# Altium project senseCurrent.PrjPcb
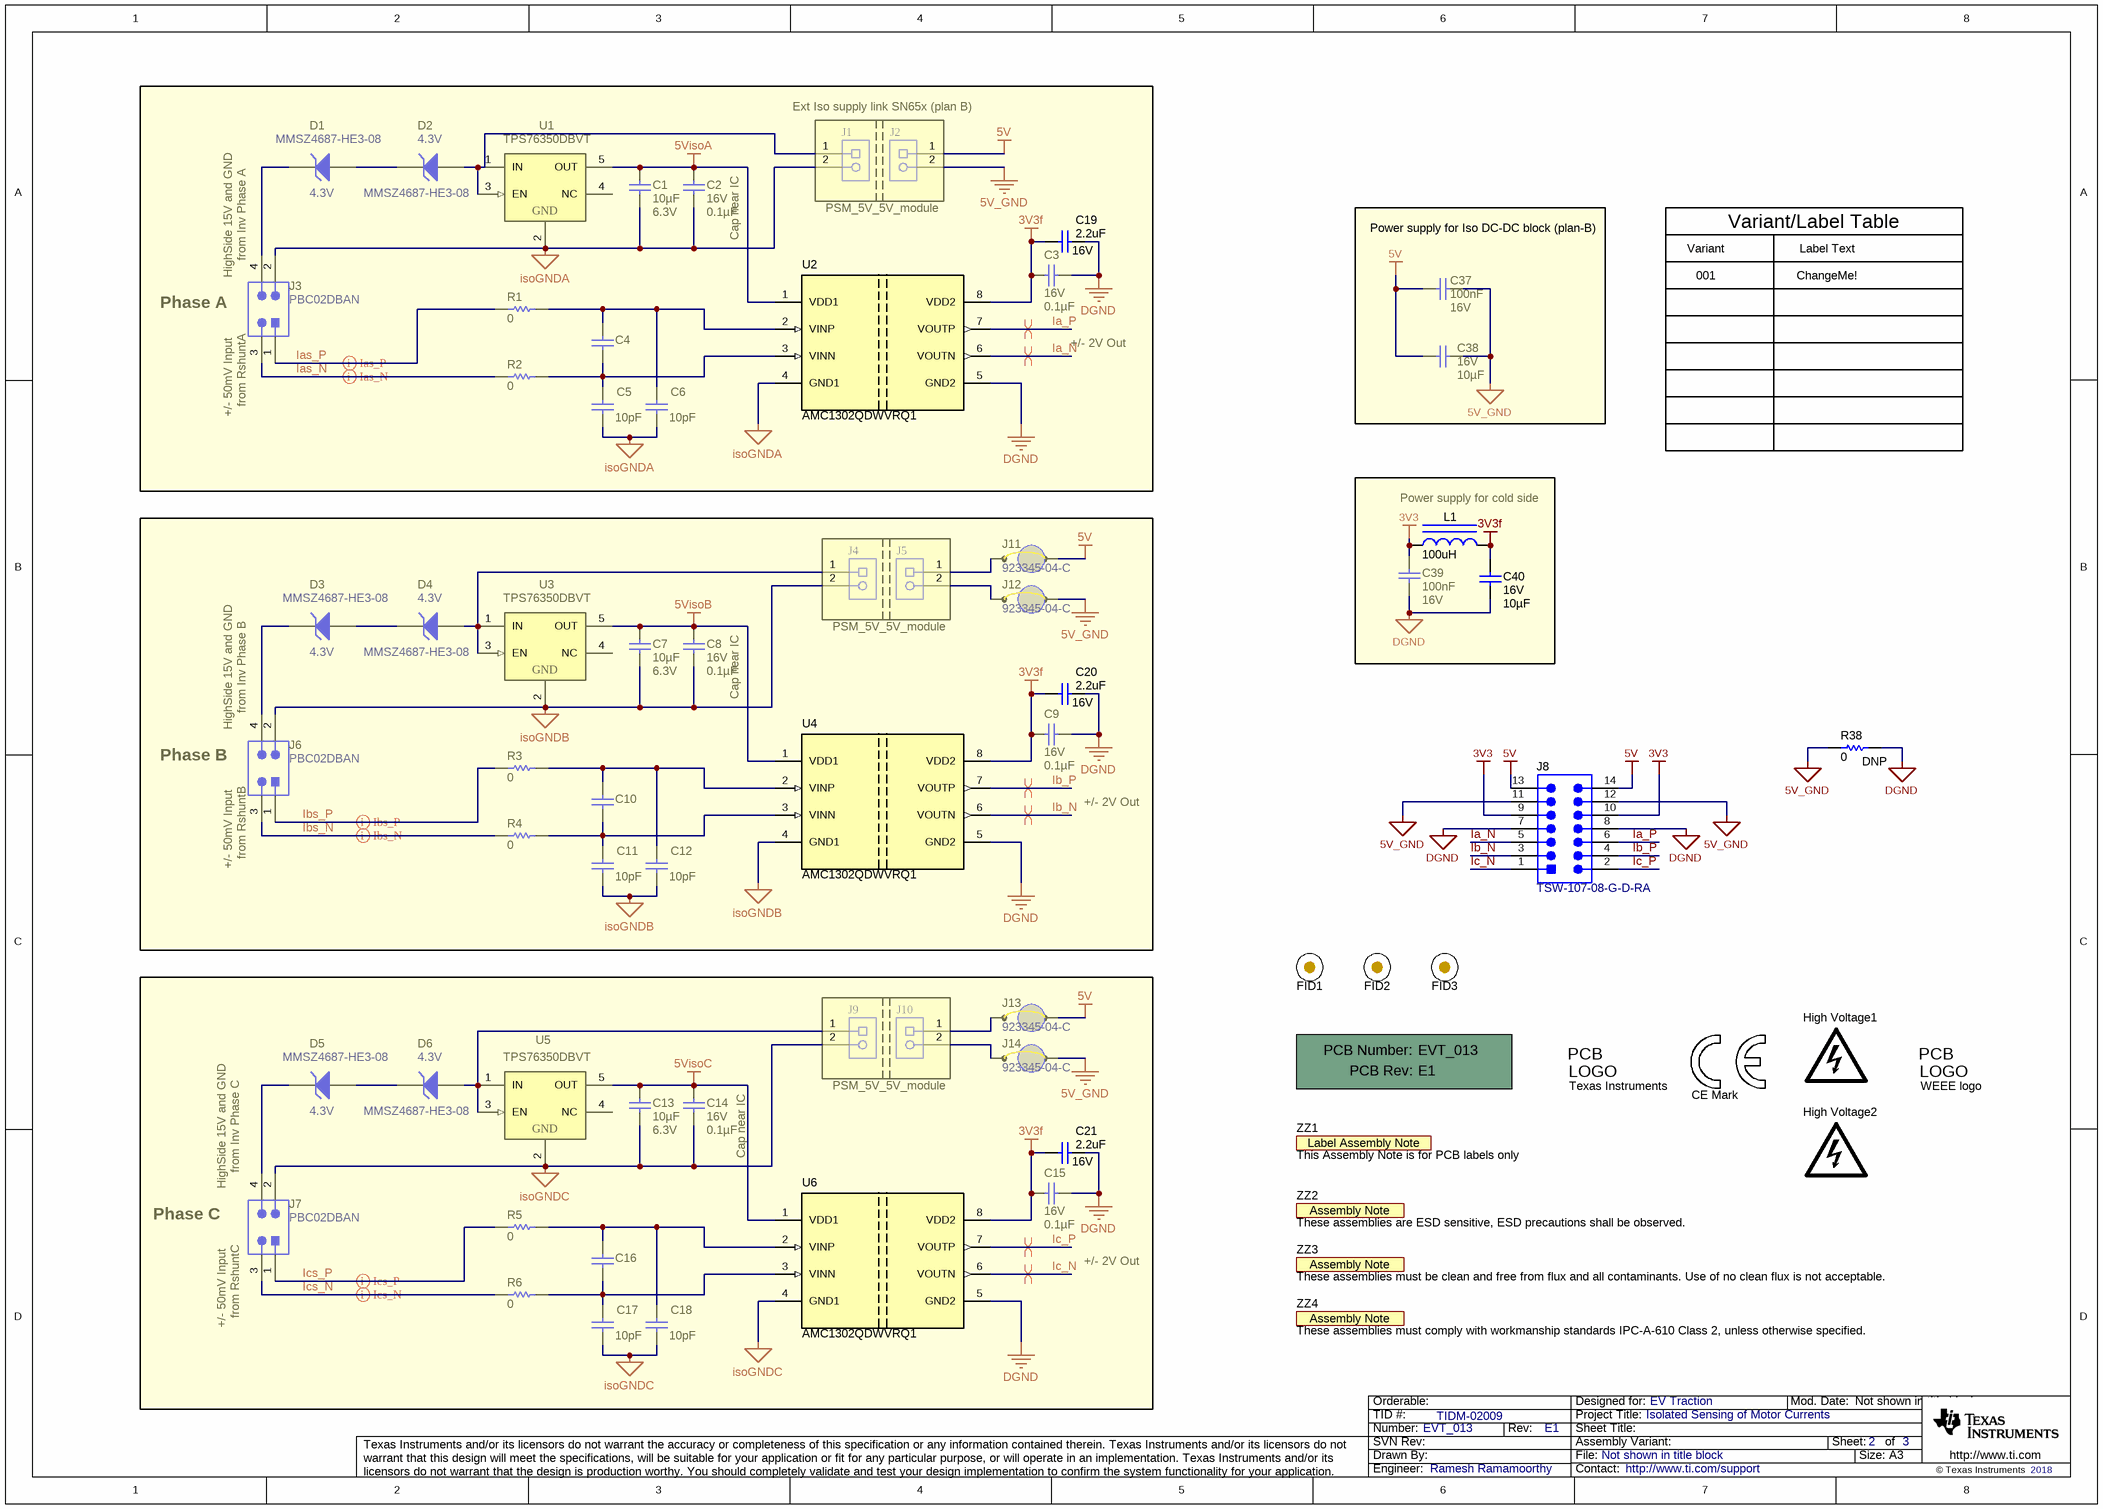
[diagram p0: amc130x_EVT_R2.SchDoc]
CopyrightYear: 2018; PCB_Layout: Ramesh Ramamoorthy; PCB_Rev: E1; PRJ_Customer: EV Traction; PRJ_Engineer: Ramesh Ramamoorthy; PRJ_Number: EVT_013; PRJ_Title: Isolated Sensing of Motor Currents; SCH_Rev: E1; TechSupport: http://www.ti.com/support; TID: TIDM-02009
1 sheet, 72 parts. Net scope: global (net labels, ports and power ports of the same name join across sheets).
Board file: amc130x_EVT_r4.PcbDoc

## Sheet amc130x_EVT_R2.SchDoc
size A3; Date: Not shown in title block; ApprovedBy: Not shown in title block; CheckedBy: Not shown in title block; Author: Not shown in title block; CompanyName: Not shown in title block; Engineer: Not shown in title block; Organization: Not shown in title block; Address1: Not shown in title block; Address2: Not shown in title block; Address3: Not shown in title block; Address4: Not shown in title block; DocumentNumber: 2; Revision: Use project parameter SCH_Rev; SheetNumber: 2; SheetTotal: 3; PageSetup: Record=PageOptions¦CenterHorizontal=True¦CenterVertical=True¦PrintScale=1.00¦XCorrection=1.00¦YCorrection=1.00¦PrintKind=0¦BorderSize=5000000¦LeftOffset=0¦BottomOffset=0¦Orientation=2¦PaperLength=1000¦PaperWidth=1000¦Scale=100¦PaperSource=15¦PrintQuality=600¦MediaType=1¦DitherType=10¦PaperKind=Letter¦PrintScaleMode=1

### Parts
!PCB  Printed Circuit Board  (value not drawn)  (mechanical)
C1  Cap_F: 10µF  VDC_V: 6.3V  [0805_HV]  (hidden comment: GRM21BR70J106KE76L)
C2  VDC_V: 16V  ValueDisplayed: 0.1µF  [1206]  (hidden comment: 1206YC104KAT2A)
C3  VDC_V: 16V  ValueDisplayed: 0.1µF  [1206]  (hidden comment: 1206YC104KAT2A)
C4  06035A331JAT2A  [0603]  (value not drawn)
C5  ValueDisplayed: 10pF  [0603]  (hidden comment: 06035A100JAT2A)
C6  ValueDisplayed: 10pF  [0603]  (hidden comment: 06035A100JAT2A)
C7  Cap_F: 10µF  VDC_V: 6.3V  [0805_HV]  (hidden comment: GRM21BR70J106KE76L)
C8  VDC_V: 16V  ValueDisplayed: 0.1µF  [1206]  (hidden comment: 1206YC104KAT2A)
C9  VDC_V: 16V  ValueDisplayed: 0.1µF  [1206]  (hidden comment: 1206YC104KAT2A)
C10  06035A331JAT2A  [0603]  (value not drawn)
C11  ValueDisplayed: 10pF  [0603]  (hidden comment: 06035A100JAT2A)
C12  ValueDisplayed: 10pF  [0603]  (hidden comment: 06035A100JAT2A)
C13  Cap_F: 10µF  VDC_V: 6.3V  [0805_HV]  (hidden comment: GRM21BR70J106KE76L)
C14  VDC_V: 16V  ValueDisplayed: 0.1µF  [1206]  (hidden comment: 1206YC104KAT2A)
C15  VDC_V: 16V  ValueDisplayed: 0.1µF  [1206]  (hidden comment: 1206YC104KAT2A)
C16  06035A331JAT2A  [0603]  (value not drawn)
C17  ValueDisplayed: 10pF  [0603]  (hidden comment: 06035A100JAT2A)
C18  ValueDisplayed: 10pF  [0603]  (hidden comment: 06035A100JAT2A)
C19  VDC_V: 16V  ValueDisplayed: 2.2uF  [1206]  (hidden comment: GRM31MR71C225KA35L)
C20  VDC_V: 16V  ValueDisplayed: 2.2uF  [1206]  (hidden comment: GRM31MR71C225KA35L)
C21  VDC_V: 16V  ValueDisplayed: 2.2uF  [1206]  (hidden comment: GRM31MR71C225KA35L)
C37  Cap_F: 100nF  VDC_V: 16V  [0603]  (hidden comment: CGJ3E2X7R1C104K080AA)
C38  VDC_V: 16V  ValueDisplayed: 10µF  [0603]  (hidden comment: GRM188R61C106KAALD)
C39  Cap_F: 100nF  VDC_V: 16V  [0603]  (hidden comment: CGJ3E2X7R1C104K080AA)
C40  VDC_V: 16V  ValueDisplayed: 10µF  [0603]  (hidden comment: GRM188R61C106KAALD)
D1  MMSZ4687-HE3-08  value 4.3V  [SOD-123]
D2  MMSZ4687-HE3-08  value 4.3V  [SOD-123]
D3  MMSZ4687-HE3-08  value 4.3V  [SOD-123]
D4  MMSZ4687-HE3-08  value 4.3V  [SOD-123]
D5  MMSZ4687-HE3-08  value 4.3V  [SOD-123]
D6  MMSZ4687-HE3-08  value 4.3V  [SOD-123]
FID1  Fiducial  [Fiducial10-20]  (value not drawn)
FID2  Fiducial  [Fiducial10-20]  (value not drawn)
FID3  Fiducial  [Fiducial10-20]  (value not drawn)
High_Voltage1  DANGER HIGH VOLTAGE  [IEC_HighVoltage_Small]  (value not drawn)  (no BOM)
High_Voltage2  DANGER HIGH VOLTAGE  [IEC_HighVoltage_Small]  (value not drawn)  (no BOM)
J1  5-534206-1  [CONN_534206-1]  (value not drawn)
J2  5-534206-1  [CONN_534206-1]  (value not drawn)
J3  PBC02DBAN  [Sullins_PxC02DBAN]
J4  5-534206-1  [CONN_534206-1]  (value not drawn)
J5  5-534206-1  [CONN_534206-1]  (value not drawn)
J6  PBC02DBAN  [Sullins_PxC02DBAN]
J7  PBC02DBAN  [Sullins_PxC02DBAN]
J8  TSW-107-08-G-D-RA  [TSW-107-08-G-D-RA]
J9  5-534206-1  [CONN_534206-1]  (value not drawn)
J10  5-534206-1  [CONN_534206-1]  (value not drawn)
J11  923345-04-C  [3M_923345-04-C]
J12  923345-04-C  [3M_923345-04-C]
J13  923345-04-C  [3M_923345-04-C]
J14  923345-04-C  [3M_923345-04-C]
L1  ValueDisplayed: 100uH  [MSS6122]  (hidden comment: MSS6122-104MLB)
Logo1  Texas Instruments  [TI_Stacked_Overlay_Small]  (no BOM)
Logo2  CE Mark  [CE_Mark_5mm]  (no BOM)
Logo3  WEEE logo  [WEEE_Minimum]  (no BOM)
R1  ValueDisplayed: 0  [0603]  (hidden comment: MCR03EZPJ000)
R2  ValueDisplayed: 0  [0603]  (hidden comment: MCR03EZPJ000)
R3  ValueDisplayed: 0  [0603]  (hidden comment: MCR03EZPJ000)
R4  ValueDisplayed: 0  [0603]  (hidden comment: MCR03EZPJ000)
R5  ValueDisplayed: 0  [0603]  (hidden comment: MCR03EZPJ000)
R6  ValueDisplayed: 0  [0603]  (hidden comment: MCR03EZPJ000)
R38  ValueDisplayed: 0  [0603]  (hidden comment: ERJ-3GEY0R00V)
U1  TPS76350DBVT  [DBV0005A_N]
U2  AMC1302QDWVRQ1  [DWV0008A]
U3  TPS76350DBVT  [DBV0005A_N]
U4  AMC1302QDWVRQ1  [DWV0008A]
U5  TPS76350DBVT  [DBV0005A_N]
U6  AMC1302QDWVRQ1  [DWV0008A]
ZZ1  This Assembly Note is for PCB labels only  [AssemblyNoteLabel]  (no BOM)
ZZ2  These assemblies are ESD sensitive, ESD precautions shall be observed.  [AssemblyNote]  (no BOM)
ZZ3  These assemblies must be clean and free from flux and all contaminants. Use of no clean flux is not acceptable.  [AssemblyNote]  (no BOM)
ZZ4  These assemblies must comply with workmanship standards IPC-A-610 Class 2, unless otherwise specified.  [AssemblyNote]  (no BOM)

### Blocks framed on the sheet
Phase A: C1-C6 C19 D1 D2 J3 R1 R2 U1 U2
Ext Iso supply link SN65x (plan B): J1 J2
Power supply for Iso DC-DC block (plan-B): C37 C38
Power supply for cold side: C39 C40 L1
Phase B: C7-C12 C20 D3 D4 J4-J6 J11 J12 R3 R4 U3 U4
Phase C: C13-C18 C21 D5 D6 J7 J9 J10 J13 J14 R5 R6 U5 U6

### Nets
3V3: C39.2 J8.9 J8.10 L1.1
3V3f: C3.2 C9.2 C15.2 C19.2 C20.2 C21.2 C40.2 L1.2 U2.8(VDD2) U4.8(VDD2) U6.8(VDD2)
5V: C37.2 C38.2 J2.1 J8.13 J8.14 J11.2 J13.2
5V_GND: C37.1 C38.1 J2.2 J8.11 J8.12 J12.2 J14.2 R38.1
5VisoA: C1.2 C2.1 U1.5(OUT) U2.1(VDD1)
5VisoB: C7.2 C8.1 U3.5(OUT) U4.1(VDD1)
5VisoC: C13.2 C14.1 U5.5(OUT) U6.1(VDD1)
DGND: C3.1 C9.1 C15.1 C19.1 C20.1 C21.1 C39.1 C40.1 J8.7 J8.8 R38.2 U2.5(GND2) U4.5(GND2) U6.5(GND2)
isoGNDA: C1.1 C2.2 C5.2 C6.2 J1.2 J3.2 U1.2(GND) U2.4(GND1)
isoGNDB: C7.1 C8.2 C11.2 C12.2 J4.2 J6.2 U3.2(GND) U4.4(GND1)
isoGNDC: C13.1 C14.2 C17.2 C18.2 J7.2 J9.2 U5.2(GND) U6.4(GND1)
Ia_N: J8.5 U2.6(VOUTN)
Ia_P: J8.6 U2.7(VOUTP)
Ias_N: J3.3 R2.1
Ias_P: J3.1 R1.1
Ib_N: J8.3 U4.6(VOUTN)
Ib_P: J8.4 U4.7(VOUTP)
Ibs_N: J6.3 R4.1
Ibs_P: J6.1 R3.1
Ic_N: J8.1 U6.6(VOUTN)
Ic_P: J8.2 U6.7(VOUTP)
Ics_N: J7.3 R6.1
Ics_P: J7.1 R5.1
NetC4_1: C4.1 C6.1 R1.2 U2.2(VINP)
NetC4_2: C4.2 C5.1 R2.2 U2.3(VINN)
NetC10_1: C10.1 C12.1 R3.2 U4.2(VINP)
NetC10_2: C10.2 C11.1 R4.2 U4.3(VINN)
NetC16_1: C16.1 C18.1 R5.2 U6.2(VINP)
NetC16_2: C16.2 C17.1 R6.2 U6.3(VINN)
NetD1_1: D1.1(K) J3.4
NetD1_2: D1.2(A) D2.1(K)
NetD2_2: D2.2(A) J1.1 U1.1(IN) U1.3(EN)
NetD3_1: D3.1(K) J6.4
NetD3_2: D3.2(A) D4.1(K)
NetD4_2: D4.2(A) J4.1 U3.1(IN) U3.3(EN)
NetD5_1: D5.1(K) J7.4
NetD5_2: D5.2(A) D6.1(K)
NetD6_2: D6.2(A) J9.1 U5.1(IN) U5.3(EN)
NetJ5_1: J5.1 J11.1
NetJ5_2: J5.2 J12.1
NetJ10_1: J10.1 J13.1
NetJ10_2: J10.2 J14.1

Not connected (* = marked no-connect by the designer): U1 4(NC); U3 4(NC); U5 4(NC)

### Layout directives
differential pair: Ia_N, Ia_P, Ias_N, Ias_P, Ib_N, Ib_P, Ibs_N, Ibs_P, Ic_N, Ic_P, Ics_N, Ics_P

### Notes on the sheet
- (near J3) HighSide 15V and GND
- (near J3) from Inv Phase A
- (near C2) Cap near IC
- PSM_5V_5V_module
- Variant
- Variant/Label Table
- Label Text
- 001
- ChangeMe!
- (near J3) +/- 50mV Input
- (near J3) from RshuntA
- +/- 2V Out
- (near J6) HighSide 15V and GND
- (near J6) from Inv Phase B
- (near C8) Cap near IC
- (near R38) DNP
- (near J6) +/- 50mV Input
- (near J6) from RshuntB
- (near J7) HighSide 15V and GND
- (near J7) from Inv Phase C
- (near C14) Cap near IC
- (near J7) +/- 50mV Input
- (near J7) from RshuntC

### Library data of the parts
!PCB = CMP-0003618-2: Manufacturer: Any; PartNumber: EVT_013
C1 C7 C13 = CMP-0008311-2: CAP, CERM, 10 uF, 6.3 V, +/- 10%, X7R, 0805; Manufacturer: MuRata; TaMin_C: -55°C; Polarized: N; SizeAreaWB_mm2: 6.75; Value1: Unknown; U/M: EA; Value: 10uF; TaMax_C: 125°C; SizeZ_mm: 1.45; SizeX_mm: 2; SizeY_mm: 1.25; Cap_Case: 0805; SizeArea_mm2: 2.5; AEC Category: Q200
C2 C3 C8 C9 C14 C15 = CMP-0860522-1: CAP, CERM, 0.1 µF, 16 V,+/- 10%, X7R, 1206; Manufacturer: AVX; SizeArea_mm2: 5.12; SizeX_mm: 3.2; Value: 0.1uF; SizeAreaWB_mm2: 10.92; Cap_F: 100nF; SizeZ_mm: 1.35; AEC Category: Q200; Polarized: N; U/M: EA; SizeY_mm: 1.6; TaMin_C: -55°C; TaMax_C: 125°C
C4 C10 C16 = CMP-0006784-4: CAP, CERM, 330 pF, 50 V, +/- 5%, C0G/NP0, 0603; Manufacturer: AVX; TaMin_C: -55°C; ESR_ohm: 0.071; Polarized: N; SizeAreaWB_mm2: 4.68; Value1: 0.071 ohm; U/M: EA; Value: 330pF; TaMax_C: 125°C; SizeZ_mm: 1; SizeX_mm: 1.6; SizeY_mm: 0.8; Value2: 50V; SizeArea_mm2: 1.28; AEC Category: Q200
C5 C6 C11 C12 C17 C18 = CMP-0006761-4: CAP, CERM, 10 pF, 50 V, +/- 5%, C0G/NP0, 0603; Manufacturer: AVX; Polarized: N; Value: 10pF; U/M: EA; ESR_ohm: 4.03d; Value1: 0.403 ohm; VDC_V: 50V; TaMin_C: -55°C; TaMax_C: 125°C; AEC Category: Q200; SizeArea_mm2: 1.28; SizeAreaWB_mm2: 4.68; SizeX_mm: 1.6; SizeY_mm: 0.8; SizeZ_mm: 1
C19-C21 = CMP-0008987-1: CAP, CERM, 2.2 uF, 16 V, +/- 10%, X7R, 1206; Manufacturer: MuRata; TaMin_C: -55°C; ESR_ohm: 6m; Polarized: N; SizeAreaWB_mm2: 10.92; Value1: 0.006 ohm; U/M: EA; Value: 2.2uF; TaMax_C: 125°C; SizeZ_mm: 1.35; SizeX_mm: 3.2; SizeY_mm: 1.6; SizeArea_mm2: 5.12; Cap_F: 2.2µF; AEC Category: Q200
C37 C39 = CMP-0007106-4: CAP, CERM, 0.1 uF, 16 V, +/- 10%, X7R, AEC-Q200 Grade 1, 0603; Manufacturer: TDK; TaMin_C: -55°C; Polarized: N; SizeAreaWB_mm2: 4.68; Value1: Unknown; U/M: EA; Value: 0.1uF; TaMax_C: 125°C; SizeZ_mm: 1; SizeX_mm: 1.6; SizeY_mm: 0.8; SizeArea_mm2: 1.28; AEC Qualified: Y; AEC Category: Q200
C38 C40 = CMP-0086225-1: CAP, CERM, 10 µF, 16 V,+/- 10%, X5R, 0603; Manufacturer: MuRata; SizeZ_mm: 1; SizeX_mm: 1.6; SizeArea_mm2: 1.28; U/M: EA; AEC Category: Q200; SizeY_mm: 0.8; Polarized: N; TaMax_C: 85°C; Value: 10uF; SizeAreaWB_mm2: 4.68; TaMin_C: -55°C
D1-D6 = CMP-0077560-1: Diode, Zener, 4.3 V, 500 mW, AEC-Q101, SOD-123; Manufacturer: Vishay-Semiconductor; SizeAreaWB_mm2: 13.095; SizeArea_mm2: 6.545; AEC Qualified: Y; AEC Category: Q101; SizeZ_mm: 1.35; RJA_CperW: 340; Power_W: 500mW; SizeY_mm: 1.7; U/M: EA; Value1: 0.5W; SizeX_mm: 3.85
FID1-FID3 = CMP-0077181-1: Fiducial mark.  There is nothing to buy or mount.
High_Voltage1 High_Voltage2 = CMP-0074835-1: IEC 61010-1 High Voltage Warning; SymbolCreator: a0412235
J1 J2 J4 J5 J9 J10 = CMP-0054836-1: Connector, Receptacle, 100mil, 2x1, Gold plated, TH; Manufacturer: TE Connectivity; CNHeader: FALSE; Green_Lifecycle: Active; Green_REACh: Passed
J3 J6 J7 = CMP-0054605-1: Header, 2.54mm, 2x2, Gold, R/A, TH; Manufacturer: Sullins Connector Solutions; CNHeader: TRUE; Current_A: 3A; Shrouded: N; Gender: Male; Voltage_V: 1.8kV; Row_Count: 2; RowSpacing_mm: 2.54; CT: FALSE; Cert_UL: Y
J8 = CMP-0075417-2: Header, 100mil, 7x2, Gold, R/A, TH; Manufacturer: Samtec; Pitch_mm: 2.54; Cert_VDE: N; Gender: Male; Cert_CSA: Y; Current_A: 6.3A; Voltage_V: 550V; Row_Count: 2
J11-J14 = CMP-0075057-1: Jumper Wire, 400 mil Spacing, Yellow, Pkg of 200; Manufacturer: 3M; CNHeader: False; Green_Lifecycle: Active; Green_REACh: Passed
L1 = CMP-0061563-2: Inductor, Shielded Drum Core, Ferrite, 100 uH, 0.4 A, 1.37 ohm, SMD; Manufacturer: Coilcraft; Isat: 0.4A @ 30% inductance drop; Irms: 0.5A @ 40C rise; Green_Lifecycle: Not Set; SizeAreaWB_mm2: 65.61; DCR_ohm: 1.37; Green_REACh: Incomplete; Value: 100uH; Imax_A: 400mA; SizeZ_mm: 2.2; SizeX_mm: 6.1; Value2: 0.4A; SizeArea_mm2: 37.21; Ind_H: 100µH; AEC Category: Q200
Logo1 = CMP-0074838-1: Texas Instrument Corporate Signature; SymbolCreator: a0412235; Lib Reference: TI_Logo; Library Reference: Logo
Logo2 = CMP-0074844-1: SymbolCreator: a0412235
Logo3 = CMP-0074769-1
R1-R6 = CMP-0025883-3: RES, 0, 5%, 0.1 W, 0603; Manufacturer: Rohm; Value: 0; Value_Code: 0000; Power_W: 100mW; Value2: 0.1W; VDC_V: 50V; TempCo: 400 ppm/C; EIA_Code: E24; U/M: EA; AEC Category: Q200; AEC Qualified: N; SizeArea_mm2: 1.28; SizeX_mm: 1.6; SizeY_mm: 0.8; SizeZ_mm: 1
R38 = CMP-0025874-1: RES, 0, 5%, 0.1 W, 0603; Manufacturer: Panasonic; Power_W: 100mW; TempCo: 600 ppm/C; Value_Code: 0000; U/M: EA; Value: 0; EIA_Code: E24; SizeX_mm: 1.6; SizeY_mm: 0.8; SizeZ_mm: 1; Value2: 0.1W; SizeArea_mm2: 1.28; VDC_V: 50V; AEC Category: Q200
U1 U3 U5 = CMP-0035557-1: Single Output LDO, 150 mA, Fixed 5 V Output, 2.7 to 10 V Input, with Low IQ, 5-pin SOT-23 (DBV), -40 to 125 degC, Green (RoHS & no Sb/Br); Manufacturer: Texas Instruments; SubFamily: Single Channel LDO; Vin(Max)(V): 10; Vdo(Typ)(mV): 300; Vout Adj(Max)(V): 5; Vin(Min)(V): 2.7; Iout(Max)(A): 0.15; Iq(Typ)(mA): 0.08; Accuracy(%): 3
U2 U4 U6 = CMP-0080587-1: Precision Reinforced Isolated Amplifier for Current Sensing, DWV0008A (SOIC-8); Alternate Manufacturer: Texas Instruments; SizeAreaWB_mm2: 105.975; SizeZ_mm: 2.8; SizeX_mm: 11.5; SizeY_mm: 5.85; SizeArea_mm2: 67.275; CompType: IC; AEC Qualified: Y; AEC Category: Q200
ZZ1 = CMP-0003616-3
ZZ2 = CMP-0077236-1
ZZ3 = CMP-0077237-1
ZZ4 = CMP-0077238-1

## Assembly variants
001: not fitted FID1 FID2 FID3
